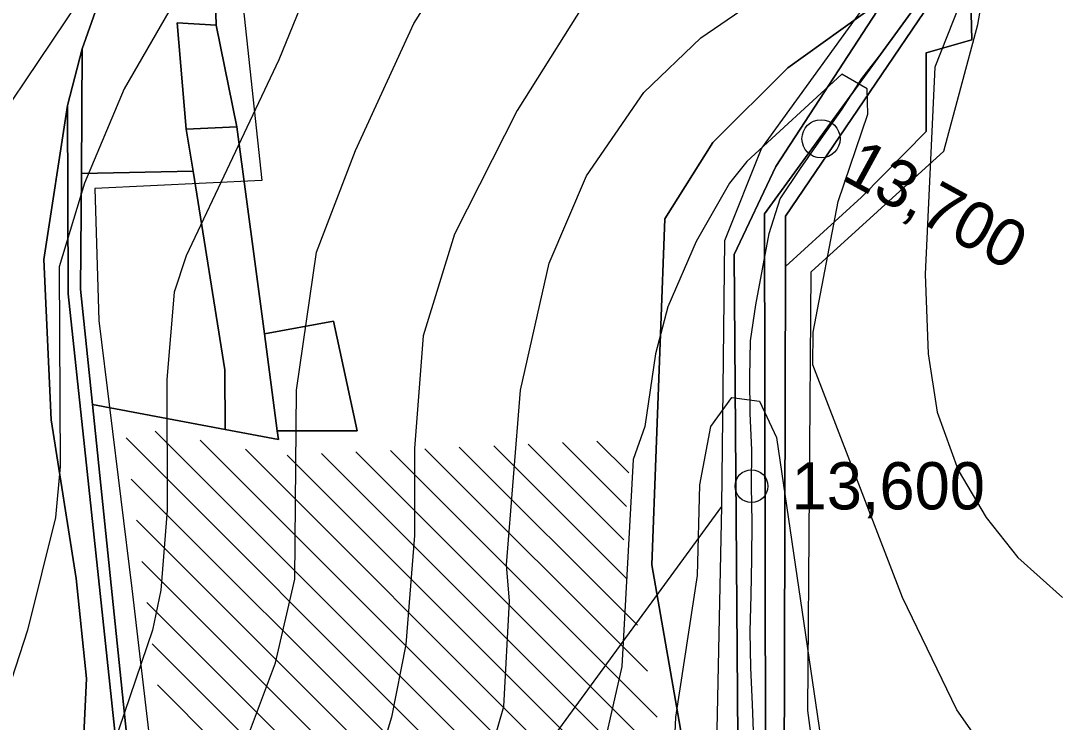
# Model space of a CAD drawing. Extents: x -510989 to -501240, y -1184665 to -1176089.
# Drawn here: x -510333.4 to -510047.2, y -1177572.4 to -1177379.3 of the extents above; entities that cross this region are included whole.
import ezdxf

# ---------------------------------------------------------------- set-up
doc = ezdxf.new("R2010")
doc.units = 0
for name, color, linetype in [('lesni_pozemek', 7, 'Continuous'), ('NAVRH_revitalizace_toku', 7, 'Continuous'), ('orna_puda', 7, 'Continuous'), ('ostatni_plocha_x_neplodna_puda', 7, 'Continuous'), ('ostatni_plocha_x_ostatni_komunikace', 7, 'Continuous'), ('STAV_erozne_ohrozene_plochy', 7, 'Continuous'), ('STAV_systematicke_odvodneni', 7, 'Continuous'), ('trasovani_toku', 7, 'Continuous'), ('trvaly_travni_porost', 7, 'Continuous'), ('vrstevnice_01', 7, 'Continuous'), ('vrstevnice_02', 7, 'Continuous'), ('zahrada', 7, 'Continuous'), ('zastavena_plocha_a_nadvori', 7, 'Continuous')]:
    doc.layers.add(name, color=color, linetype=linetype)

msp = doc.modelspace()

# ---------------------------------------------------------------- linework, layer by layer
at = {"layer": 'lesni_pozemek'}
msp.add_lwpolyline([(-510309.3, -1177366.43), (-510316.48, -1177386.96), (-510320.51, -1177402.61), (-510327.09, -1177444.96), (-510325.02, -1177489.16), (-510318.12, -1177532.77), (-510315.28, -1177560.29), (-510317.43, -1177604.64), (-510308.17, -1177628.21), (-510299, -1177639.71), (-510294.12, -1177637.73), (-510292.61, -1177637.11), (-510252.56, -1177713.54), (-510234.53, -1177782.61), (-510204.29, -1177845.51), (-510190.74, -1177869.24), (-510187.26, -1177882.35), (-510185.29, -1177933.82), (-510187.83, -1177934.64), (-510189.41, -1177934.52), (-510198.81, -1177963.46)], dxfattribs=at)
at = {"layer": 'NAVRH_revitalizace_toku'}
for points in [[(-510059.86, -1177739.28), (-510064.11, -1177717.17), (-510112.6, -1177601.48), (-510116.86, -1177569.15), (-510116, -1177448.36), (-510079.43, -1177415.19), (-510070.07, -1177380.31), (-510064.11, -1177346.29), (-510049.65, -1177288.44)], [(-510075.17, -1177292.7), (-510089.63, -1177359.05), (-510129.61, -1177414.34), (-510139.82, -1177439.86), (-510140.67, -1177513.01), (-510142.37, -1177596.38), (-510119.41, -1177649.97), (-510081.13, -1177743.53)], [(-510140.67, -1177513.01), (-510191.39, -1177582.56), (-510191.34, -1177752.07)]]:
    msp.add_lwpolyline(points, dxfattribs=at)
at = {"layer": 'orna_puda'}
for points in [[(-509903.08, -1177271.99), (-509906.47, -1177405.26), (-509907.24, -1177447.42), (-509919.35, -1177521.3), (-509940.02, -1177559.56), (-509932.88, -1177599.21), (-509966.13, -1177637.97), (-509980.54, -1177661.84), (-509986.51, -1177693.69), (-510011.12, -1177708.83), (-510046.21, -1177724.59), (-510065.83, -1177729.25), (-510067.57, -1177729.21), (-510116.51, -1177610.57), (-510123.38, -1177588.75), (-510123.04, -1177446.95), (-510102.14, -1177427.79), (-510084.34, -1177409.75), (-510084.36, -1177388.11), (-510071.74, -1177384.51), (-510072, -1177373.55)], [(-510300.9, -1177608.36), (-510313.63, -1177484.87), (-510277.14, -1177491.79), (-510262.51, -1177494.56), (-510262.83, -1177492.16), (-510240.82, -1177492.16), (-510247.36, -1177461.94), (-510266.37, -1177465.44), (-510273.92, -1177408.51), (-510279.65, -1177380.46), (-510280.39, -1177354.79)], [(-510098.1, -1177374.8), (-510122.35, -1177392.2), (-510143.03, -1177412.76), (-510156.18, -1177433.8), (-510159.77, -1177529), (-510151.28, -1177577.98), (-510134.26, -1177652.15), (-510120.32, -1177683.49), (-510091.19, -1177737.71), (-510089.47, -1177740.92), (-510088.06, -1177744.6), (-510083.05, -1177757.65), (-510079.86, -1177770.71), (-510075.01, -1177796.11), (-510072.6, -1177817.38), (-510064.11, -1177816.33), (-510064.11, -1177834.11), (-510079.43, -1177947.66), (-510079.36, -1177956.75)]]:
    msp.add_lwpolyline(points, dxfattribs=at)
msp.add_lwpolyline([(-510316.73, -1177421.27), (-510286.01, -1177420.69), (-510277.23, -1177475.4), (-510277.14, -1177491.79), (-510313.63, -1177484.87), (-510316.96, -1177453.2)], close=True, dxfattribs=at)
at = {"layer": 'ostatni_plocha_x_neplodna_puda'}
for points in [[(-510069.84, -1177344.42), (-510072, -1177373.55), (-510071.74, -1177384.51), (-510084.36, -1177388.11), (-510084.34, -1177409.75), (-510102.14, -1177427.79), (-510123.04, -1177446.95), (-510123.01, -1177433.04), (-510079.88, -1177369.48)], [(-510327.09, -1177444.96), (-510320.51, -1177402.61), (-510320.38, -1177454.43), (-510315.9, -1177496.43), (-510308.93, -1177561.88), (-510303.6, -1177611.95), (-510294.12, -1177637.73), (-510299, -1177639.71), (-510308.17, -1177628.21), (-510317.43, -1177604.64), (-510315.28, -1177560.29), (-510318.12, -1177532.77), (-510325.02, -1177489.16)]]:
    msp.add_lwpolyline(points, close=True, dxfattribs=at)
at = {"layer": 'ostatni_plocha_x_ostatni_komunikace'}
for points in [[(-510082.36, -1177368.53), (-510128.78, -1177432.41), (-510128.56, -1177578.38), (-510126.42, -1177589.11), (-510120.67, -1177608.13), (-510074.05, -1177731.54), (-510072.41, -1177734.85), (-510077.22, -1177736.56), (-510078.83, -1177733.26), (-510136, -1177589.03), (-510137.13, -1177443.58), (-510125.71, -1177419.39), (-510083.15, -1177353.98)], [(-510079.88, -1177369.48), (-510123.01, -1177433.04), (-510123.04, -1177446.95), (-510123.38, -1177588.75), (-510116.51, -1177610.57), (-510067.57, -1177729.21), (-510074.05, -1177731.54), (-510120.67, -1177608.13), (-510126.42, -1177589.11), (-510128.56, -1177578.38), (-510128.78, -1177432.41), (-510082.36, -1177368.53)]]:
    msp.add_lwpolyline(points, dxfattribs=at)
msp.add_lwpolyline([(-510320.51, -1177402.61), (-510316.48, -1177386.96), (-510316.73, -1177421.27), (-510316.96, -1177453.2), (-510313.63, -1177484.87), (-510300.9, -1177608.36), (-510292.61, -1177637.11), (-510294.12, -1177637.73), (-510303.6, -1177611.95), (-510308.93, -1177561.88), (-510315.9, -1177496.43), (-510320.38, -1177454.43)], close=True, dxfattribs=at)
at = {"layer": 'STAV_erozne_ohrozene_plochy'}
for p, q in [((-510296.42, -1177492.22), (-510141.77, -1177646.86)), ((-510304.42, -1177494.12), (-510137.23, -1177661.31)), ((-510284.02, -1177494.72), (-510144.52, -1177634.21)), ((-510193.83, -1177495.82), (-510167.46, -1177522.18)), ((-510184.36, -1177495.39), (-510166.78, -1177512.96)), ((-510174.89, -1177494.96), (-510166.1, -1177503.75)), ((-510271.61, -1177497.23), (-510147.28, -1177621.56)), ((-510260.12, -1177498.82), (-510150.03, -1177608.91)), ((-510250.65, -1177498.39), (-510152.78, -1177596.26)), ((-510241.18, -1177497.96), (-510155.53, -1177583.61)), ((-510231.71, -1177497.53), (-510158.28, -1177570.96)), ((-510222.24, -1177497.1), (-510161.03, -1177558.31)), ((-510212.77, -1177496.67), (-510163.78, -1177545.66)), ((-510203.3, -1177496.24), (-510166.54, -1177533.01)), ((-510302.99, -1177505.45), (-510127.12, -1177681.32)), ((-510301.56, -1177516.78), (-510117.01, -1177701.33)), ((-510300.13, -1177528.11), (-510106.9, -1177721.34)), ((-510298.69, -1177539.44), (-510097.75, -1177740.39)), ((-510297.26, -1177550.77), (-510091.21, -1177756.83)), ((-510295.83, -1177562.1), (-510085.59, -1177772.34))]:
    msp.add_line(p, q, dxfattribs=at)
at = {"layer": 'STAV_systematicke_odvodneni'}
for p, q in [((-510273.99, -1177358.56), (-510267.04, -1177423.26)), ((-510267.04, -1177423.26), (-510313.01, -1177425.4)), ((-510313.01, -1177425.4), (-510311.94, -1177461.76)), ((-510311.94, -1177461.76), (-510302.85, -1177535.56)), ((-510302.85, -1177535.56), (-510298.04, -1177576.2))]:
    msp.add_line(p, q, dxfattribs=at)
at = {"layer": 'trasovani_toku'}
for p, q in [((-510095.9, -1177387.31), (-510090, -1177379.23)), ((-510102.06, -1177395.19), (-510095.9, -1177387.31)), ((-510107.43, -1177403.62), (-510102.06, -1177395.19)), ((-510113.24, -1177411.76), (-510107.43, -1177403.62)), ((-510118.93, -1177419.98), (-510113.24, -1177411.76)), ((-510124.46, -1177428.32), (-510118.93, -1177419.98)), ((-510127.54, -1177437.83), (-510124.46, -1177428.32)), ((-510129.34, -1177447.66), (-510127.54, -1177437.83)), ((-510131.22, -1177457.49), (-510129.34, -1177447.66)), ((-510132.66, -1177467.38), (-510131.22, -1177457.49)), ((-510132.8, -1177477.38), (-510132.66, -1177467.38)), ((-510132.78, -1177487.38), (-510132.8, -1177477.38)), ((-510132.27, -1177497.37), (-510132.78, -1177487.38)), ((-510132.38, -1177507.37), (-510132.27, -1177497.37)), ((-510132.17, -1177517.36), (-510132.38, -1177507.37)), ((-510132.29, -1177527.36), (-510132.17, -1177517.36)), ((-510132.47, -1177537.36), (-510132.29, -1177527.36)), ((-510132.76, -1177547.36), (-510132.47, -1177537.36)), ((-510132.52, -1177557.36), (-510132.76, -1177547.36)), ((-510132.09, -1177567.35), (-510132.52, -1177557.36)), ((-510131.73, -1177577.34), (-510132.09, -1177567.35))]:
    msp.add_line(p, q, dxfattribs=at)
for centre, radius in [((-510113.24, -1177411.76), 5.25), ((-510132.38, -1177507.37), 4.5)]:
    msp.add_circle(centre, radius, dxfattribs=at)
at = {"layer": 'trvaly_travni_porost'}
for points in [[(-510082.63, -1177292.86), (-510070.28, -1177289.5), (-510083.15, -1177353.98), (-510125.71, -1177419.39), (-510137.13, -1177443.58), (-510136, -1177589.03), (-510078.83, -1177733.26), (-510091.19, -1177737.71), (-510120.32, -1177683.49), (-510134.26, -1177652.15), (-510151.28, -1177577.98), (-510159.77, -1177529), (-510156.18, -1177433.8), (-510143.03, -1177412.76), (-510122.35, -1177392.2), (-510098.1, -1177374.8), (-510093.86, -1177366.32), (-510095.14, -1177356.56), (-510093.39, -1177342.83)], [(-510287.86, -1177409.13), (-510273.92, -1177408.51), (-510266.37, -1177465.44), (-510262.83, -1177492.16), (-510262.51, -1177494.56), (-510277.14, -1177491.79), (-510277.23, -1177475.4), (-510286.01, -1177420.69)], [(-510247.36, -1177461.94), (-510240.82, -1177492.16), (-510262.83, -1177492.16), (-510266.37, -1177465.44)]]:
    msp.add_lwpolyline(points, close=True, dxfattribs=at)
at = {"layer": 'vrstevnice_01'}
for points in [[(-510041.19, -1177289), (-510081.91, -1177392), (-510084.59, -1177449), (-510083.81, -1177471), (-510081.31, -1177487), (-510075.5, -1177503), (-510067.81, -1177516), (-510059.09, -1177527), (-510046.81, -1177538)], [(-510266.31, -1177331), (-510305, -1177398), (-510315.91, -1177424), (-510322.81, -1177447), (-510322.59, -1177502), (-510323.81, -1177516), (-510331.59, -1177547), (-510337.09, -1177564), (-510345.69, -1177611), (-510346.41, -1177620), (-510343.69, -1177657), (-510328.59, -1177712), (-510318.69, -1177755), (-510314.09, -1177797), (-510315.69, -1177842), (-510325.5, -1177910), (-510323.5, -1177988)], [(-510253.09, -1177986), (-510262.41, -1177945), (-510263, -1177924), (-510251.59, -1177847), (-510250.69, -1177806), (-510253.69, -1177760), (-510259.69, -1177728), (-510267.81, -1177699), (-510285.69, -1177654), (-510291, -1177636), (-510291, -1177616), (-510288.91, -1177610), (-510272.69, -1177581), (-510263.31, -1177556), (-510258, -1177533), (-510257.5, -1177481), (-510252, -1177443), (-510241.31, -1177415), (-510225.31, -1177380), (-510201.91, -1177343)], [(-510162, -1177399), (-510146.31, -1177384), (-510126.09, -1177370)], [(-510182.59, -1178002), (-510190.31, -1177949), (-510194.09, -1177908), (-510190.91, -1177869), (-510190.69, -1177844), (-510192.81, -1177777), (-510195.69, -1177731), (-510199.81, -1177701), (-510207.69, -1177666), (-510211, -1177657), (-510215.91, -1177636), (-510215.5, -1177620), (-510200.5, -1177568), (-510198.91, -1177539), (-510199.81, -1177529), (-510195.91, -1177481), (-510188, -1177446), (-510177.81, -1177422), (-510162, -1177399)], [(-510130.59, -1177957), (-510131.09, -1177933), (-510129.41, -1177919), (-510122.09, -1177885), (-510119.5, -1177865), (-510121.59, -1177813), (-510125.59, -1177775), (-510131.81, -1177737), (-510146.09, -1177669), (-510153.41, -1177614), (-510154.31, -1177596), (-510153.19, -1177571), (-510147.19, -1177532), (-510146.59, -1177507), (-510143.59, -1177491), (-510137.81, -1177483), (-510130.19, -1177484), (-510125.5, -1177494), (-510113.31, -1177577), (-510111.31, -1177582), (-510082.41, -1177617), (-510042, -1177650)]]:
    msp.add_lwpolyline(points, dxfattribs=at)
at = {"layer": 'vrstevnice_02'}
for points in [[(-510174.91, -1177369), (-510196.81, -1177404), (-510214.09, -1177438), (-510222.69, -1177466), (-510225.09, -1177497), (-510225.09, -1177521), (-510227.5, -1177551), (-510231.41, -1177571), (-510238.91, -1177596), (-510245.5, -1177614), (-510247.41, -1177633), (-510244.69, -1177646), (-510234.69, -1177674), (-510229.59, -1177692), (-510222.69, -1177732), (-510218.81, -1177808), (-510218.91, -1177842), (-510227.31, -1177918), (-510227.59, -1177933), (-510225, -1177961)], [(-510254.69, -1177371), (-510262.41, -1177390), (-510287.91, -1177444), (-510291.19, -1177454), (-510293.19, -1177478), (-510293.09, -1177514), (-510294.91, -1177536), (-510297.19, -1177547), (-510311.09, -1177588), (-510316.41, -1177612), (-510318, -1177642), (-510316.41, -1177655), (-510305.31, -1177690), (-510296.41, -1177724), (-510294.59, -1177726), (-510287.69, -1177756), (-510279.09, -1177824), (-510279.31, -1177861), (-510285.09, -1177897), (-510291.81, -1177925), (-510293.81, -1177941), (-510293.09, -1177957)], [(-510357, -1177998), (-510358.09, -1177933), (-510352.5, -1177854), (-510352.31, -1177793), (-510355.69, -1177761), (-510373.31, -1177682), (-510377, -1177671), (-510384.31, -1177633), (-510385.59, -1177620), (-510383.19, -1177591), (-510370.59, -1177551), (-510366.31, -1177525), (-510366.81, -1177503), (-510369.41, -1177487), (-510368.41, -1177466), (-510363.91, -1177447), (-510354.81, -1177433), (-510350.41, -1177423), (-510317.41, -1177374)], [(-510065.31, -1177584), (-510075.91, -1177569), (-510090.81, -1177538), (-510115.5, -1177474), (-510115.41, -1177465), (-510108.5, -1177429), (-510100.41, -1177405), (-510100.59, -1177398), (-510107.5, -1177394), (-510133.69, -1177418), (-510138.41, -1177424), (-510147.59, -1177440), (-510155.41, -1177458), (-510158.81, -1177471), (-510161.69, -1177491), (-510164.91, -1177500), (-510168, -1177557), (-510175.31, -1177589)]]:
    msp.add_lwpolyline(points, dxfattribs=at)
at = {"layer": 'zahrada'}
msp.add_lwpolyline([(-510279.65, -1177380.46), (-510273.92, -1177408.51), (-510287.86, -1177409.13), (-510290.37, -1177379.88)], close=True, dxfattribs=at)
at = {"layer": 'zastavena_plocha_a_nadvori'}
msp.add_lwpolyline([(-510290.41, -1177357.42), (-510280.39, -1177354.79), (-510279.65, -1177380.46), (-510290.37, -1177379.88), (-510287.86, -1177409.13), (-510286.01, -1177420.69), (-510316.73, -1177421.27), (-510316.48, -1177386.96), (-510309.3, -1177366.43), (-510310.07, -1177364.2), (-510308.17, -1177363.54)], close=True, dxfattribs=at)

# ---------------------------------------------------------------- texts
at = {"layer": 'trasovani_toku'}
msp.add_text('13,700', height=13, rotation=331.3794, dxfattribs=at).set_placement((-510108.08, -1177422.75))
msp.add_text('13,600', height=13, dxfattribs=at).set_placement((-510121.33, -1177513.78))

doc.saveas('drawing.dxf')
